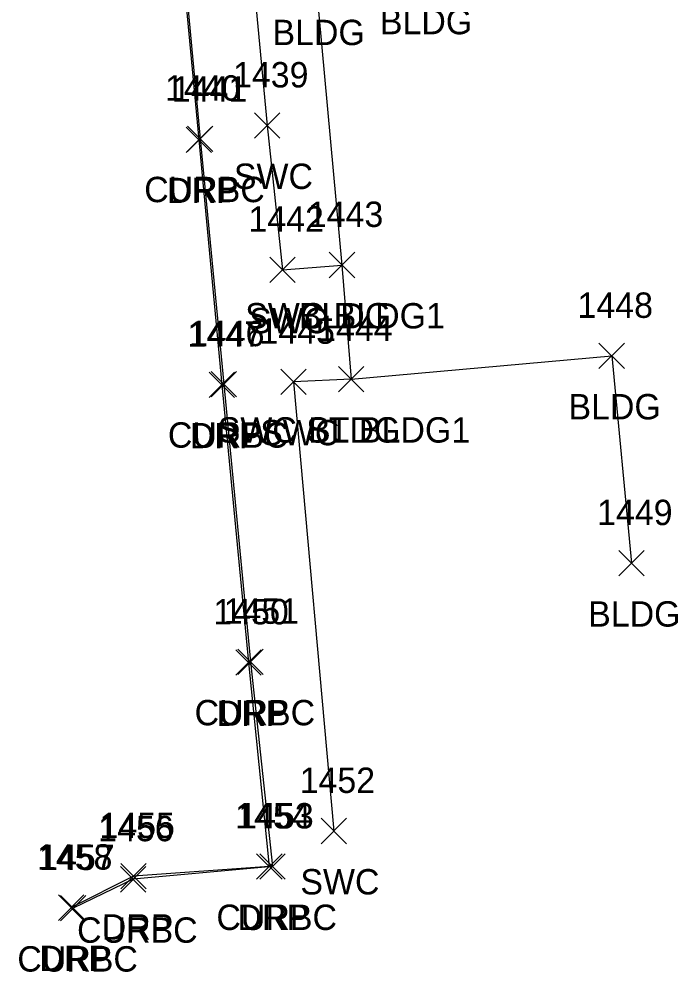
# Model space of a CAD drawing. Extents: x 1651305 to 1654558, y 539481 to 548441.
# Drawn here: x 1654505.8 to 1654557.7, y 544802.5 to 544877.6 of the extents above; entities that cross this region are included whole.
import ezdxf

# ---------------------------------------------------------------- set-up
doc = ezdxf.new("R2010")
doc.units = 0
for name, color, linetype in [('L_A', 7, 'Continuous'), ('L_I', 7, 'Continuous'), ('L_TIC', 7, 'Continuous'), ('LBC', 7, 'Continuous'), ('R_A', 7, 'Continuous'), ('R_I', 7, 'Continuous'), ('R_TIC', 7, 'Continuous'), ('RC', 7, 'Continuous'), ('RDP', 7, 'Continuous'), ('RSW', 7, 'Continuous')]:
    doc.layers.add(name, color=color, linetype=linetype)

msp = doc.modelspace()

# ---------------------------------------------------------------- linework, layer by layer
at = {"layer": 'L_TIC'}
for points in [[(1654530.235, 544857.187), (1654532.235, 544859.187)], [(1654532.235, 544857.187), (1654530.235, 544859.187)], [(1654551.508, 544850.02), (1654553.508, 544852.02)], [(1654553.508, 544850.02), (1654551.508, 544852.02)], [(1654530.968, 544848.191), (1654532.968, 544850.191)], [(1654532.968, 544848.191), (1654530.968, 544850.191)], [(1654553.063, 544833.688), (1654555.063, 544835.688)], [(1654555.063, 544833.688), (1654553.063, 544835.688)]]:
    msp.add_lwpolyline(points, dxfattribs=at)
at = {"layer": 'LBC'}
msp.add_lwpolyline([(1654545.128, 544930.807), (1654548.206, 544894.86), (1654536.16, 544893.584), (1654537.633, 544881.371), (1654529.161, 544880.516), (1654531.235, 544858.187), (1654531.968, 544849.191), (1654552.508, 544851.02), (1654554.063, 544834.688)], dxfattribs=at)
at = {"layer": 'R_TIC'}
for points in [[(1654524.344, 544868.179), (1654526.344, 544870.179)], [(1654526.344, 544868.179), (1654524.344, 544870.179)], [(1654518.941, 544867.062), (1654520.941, 544869.062)], [(1654520.941, 544867.062), (1654518.941, 544869.062)], [(1654519.052, 544867.138), (1654521.052, 544869.138)], [(1654521.052, 544867.138), (1654519.052, 544869.138)], [(1654530.235, 544857.187), (1654532.235, 544859.187)], [(1654532.235, 544857.187), (1654530.235, 544859.187)], [(1654525.55, 544856.808), (1654527.55, 544858.808)], [(1654527.55, 544856.808), (1654525.55, 544858.808)], [(1654530.968, 544848.191), (1654532.968, 544850.191)], [(1654532.968, 544848.191), (1654530.968, 544850.191)], [(1654520.747, 544847.744), (1654522.747, 544849.744)], [(1654522.747, 544847.744), (1654520.747, 544849.744)], [(1654520.919, 544847.789), (1654522.919, 544849.789)], [(1654522.919, 544847.789), (1654520.919, 544849.789)], [(1654526.418, 544847.979), (1654528.418, 544849.979)], [(1654528.418, 544847.979), (1654526.418, 544849.979)], [(1654522.862, 544825.864), (1654524.862, 544827.864)], [(1654524.862, 544825.864), (1654522.862, 544827.864)], [(1654523.024, 544825.91), (1654525.024, 544827.91)], [(1654525.024, 544825.91), (1654523.024, 544827.91)], [(1654529.589, 544812.581), (1654531.589, 544814.581)], [(1654531.589, 544812.581), (1654529.589, 544814.581)], [(1654524.503, 544809.78), (1654526.503, 544811.78)], [(1654526.503, 544809.78), (1654524.503, 544811.78)], [(1654524.747, 544809.781), (1654526.747, 544811.781)], [(1654526.747, 544809.781), (1654524.747, 544811.781)], [(1654513.797, 544809.022), (1654515.797, 544811.022)], [(1654515.797, 544809.022), (1654513.797, 544811.022)], [(1654513.755, 544808.774), (1654515.755, 544810.774)], [(1654515.755, 544808.774), (1654513.755, 544810.774)], [(1654508.868, 544806.54), (1654510.868, 544808.54)], [(1654510.868, 544806.54), (1654508.868, 544808.54)], [(1654509.042, 544806.502), (1654511.042, 544808.502)], [(1654511.042, 544806.502), (1654509.042, 544808.502)]]:
    msp.add_lwpolyline(points, dxfattribs=at)
at = {"layer": 'RC'}
msp.add_lwpolyline([(1654513.581, 544937.432), (1654514.466, 544927.512), (1654515.484, 544917.574), (1654517.4, 544896.643), (1654520.052, 544868.138), (1654521.919, 544848.789), (1654524.024, 544826.91), (1654525.747, 544810.781), (1654514.755, 544809.774), (1654510.042, 544807.502)], dxfattribs=at)
at = {"layer": 'RDP'}
msp.add_lwpolyline([(1654513.22, 544937.325), (1654514.267, 544927.515), (1654515.291, 544916.632), (1654517.258, 544896.477), (1654519.941, 544868.062), (1654521.747, 544848.744), (1654523.862, 544826.864), (1654525.503, 544810.78), (1654514.797, 544810.022), (1654509.868, 544807.54)], dxfattribs=at)
at = {"layer": 'RSW'}
for points in [[(1654519.006, 544937.969), (1654519.867, 544928.161), (1654520.792, 544918.205), (1654522.706, 544897.074), (1654525.344, 544869.179), (1654526.55, 544857.808), (1654531.235, 544858.187)], [(1654531.968, 544849.191), (1654527.418, 544848.979), (1654530.589, 544813.581)]]:
    msp.add_lwpolyline(points, dxfattribs=at)

# ---------------------------------------------------------------- texts
at = {"layer": 'L_A'}
for p in [(1654534.224, 544876.371), (1654525.751, 544875.516), (1654527.825, 544853.187), (1654549.099, 544846.02), (1654528.558, 544844.191), (1654550.653, 544829.688)]:
    msp.add_text('BLDG', height=2, dxfattribs=at).set_placement(p)
at = {"layer": 'L_I'}
for s, p in [('1443', (1654528.542, 544861.187)), ('1448', (1654549.815, 544854.02)), ('1444', (1654529.275, 544852.191)), ('1449', (1654551.362, 544837.688))]:
    msp.add_text(s, height=2, dxfattribs=at).set_placement(p)
at = {"layer": 'R_A'}
for s, p in [('SWC', (1654522.706, 544864.179)), ('CURBC', (1654515.635, 544863.138)), ('DRP', (1654517.429, 544863.062)), ('SWC BLDG1', (1654523.597, 544853.187)), ('SWC', (1654523.912, 544852.808)), ('CURBC', (1654517.502, 544843.789)), ('DRP', (1654519.235, 544843.744)), ('SWC ST BLDG1', (1654521.432, 544844.191)), ('SWC', (1654524.781, 544843.979)), ('CURBC', (1654519.607, 544821.91)), ('DRP', (1654521.35, 544821.864)), ('SWC', (1654527.951, 544808.581)), ('CURBC', (1654521.33, 544805.781)), ('DRP', (1654522.991, 544805.78)), ('CURBC', (1654510.338, 544804.774)), ('DRP', (1654512.285, 544805.022)), ('CURBC', (1654505.625, 544802.502)), ('DRP', (1654507.356, 544802.54))]:
    msp.add_text(s, height=2, dxfattribs=at).set_placement(p)
at = {"layer": 'R_I'}
for s, p in [('1439', (1654522.643, 544872.179)), ('1440', (1654517.273, 544871.138)), ('1441', (1654517.816, 544871.062)), ('1442', (1654523.857, 544860.808)), ('1443', (1654528.542, 544861.187)), ('1446', (1654519.171, 544851.789)), ('1445', (1654524.726, 544851.979)), ('1444', (1654529.275, 544852.191)), ('1447', (1654519.054, 544851.744)), ('1450', (1654521.083, 544829.864)), ('1451', (1654521.899, 544829.91)), ('1452', (1654527.896, 544816.581)), ('1454', (1654522.811, 544813.78)), ('1453', (1654523.055, 544813.781)), ('1456', (1654512.007, 544812.774)), ('1455', (1654512.104, 544813.022)), ('1458', (1654507.175, 544810.54)), ('1457', (1654507.349, 544810.502))]:
    msp.add_text(s, height=2, dxfattribs=at).set_placement(p)

doc.saveas('drawing.dxf')
